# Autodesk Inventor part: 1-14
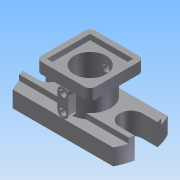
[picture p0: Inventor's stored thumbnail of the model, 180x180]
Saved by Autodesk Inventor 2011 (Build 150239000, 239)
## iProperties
Created: 2014-02
Part Number: 1-14
Document SubType Name: Modeling
Designer: Administrator
Density: 1 g/cm^3
Author: Administrator
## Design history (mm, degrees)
sketch "草图1"
  geometry: L1 (-18.455, 10.02)-(18.455, 10.02); L2 (-18.458, -10.014)-(18.458, -10.014); L3 (-15, -4.223)-(-20.571, -4.223); L4 (0, 0)-(0, 18.978); L5 (0.467, 0.003)-(27.339, 0.003); L6 (-15, 4.229)-(-20.571, 4.229); L7 (15, 4.229)-(20.571, 4.229); L8 (15, -4.223)-(20.571, -4.223); A1 r 4.226 centre (-15, 0.003) between (-15, -4.223) and (-15, 4.229); A2 r 4.226 centre (15, 0.003) between (15, 4.229) and (15, -4.223); A3 r 21 centre (0, 0) between (-18.455, 10.02) and (-20.57, 4.229); A4 r 21 centre (0, 0) between (-20.571, -4.223) and (-18.458, -10.014); A5 r 21 centre (0, 0) between (18.458, -10.014) and (20.571, -4.223); A6 r 21 centre (0, 0) between (20.57, 4.229) and (18.455, 10.02); 4 further points
  constraints: 16 end point, 13 point on circle, 7 symmetric about line, 6 centre point, 3 point on line, 1 coincident, 1 horizontal, 1 parallel, 1 perpendicular, 1 tangent, 1 other
  dimensions: "d27" = 20.03478 distance between parallel lines of L1 L2; "d29" = 30 diameter of A1.centre L4
extrude "拉伸1" new body sketch "草图1" distance "d0" = 6; taper "d1" = 0 deg
sketch "草图2"
  geometry: C1 r 7.5 at (0, 0); 1 further point
  constraints: 1 centre point, 1 coincident
  dimensions: "d2" = 15 diameter of C1
extrude "拉伸2" join sketch "草图2" distance "d3" = 10; taper "d4" = 0 deg
sketch "草图3"
  geometry: L1 (-9.935, -9.95)-(9.935, -9.95); L2 (9.935, -9.95)-(9.935, 9.921); L3 (9.935, 9.921)-(-9.935, 9.921); L4 (-9.935, 9.921)-(-9.935, -9.95); C1 r 7.5 at (0, 0) reference; 1 further point
  constraints: 8 end point, 2 parallel, 1 horizontal, 1 midpoint, 1 perpendicular, 1 vertical alignment
  dimensions: "d5" = 19.87123 distance of L1.end L2.end; "d6" = 19.871 distance of L2.end L3.end
extrude "拉伸3" join sketch "草图3" distance "d7" = 4; taper "d8" = 0 deg
fillet "圆角1" dims "d9" = 2
fillet "圆角2" dims "d10" = 2
sketch "草图4"
  geometry: L1 (-7.935, -7.95)-(7.935, -7.95); L2 (7.935, -7.95)-(7.935, 7.921); L3 (7.935, 7.921)-(-7.935, 7.921); L4 (-7.935, 7.921)-(-7.935, -7.95); A1 r 2 centre (-7.935, -7.95) between (-9.935, -7.95) and (-7.935, -9.95) reference; A2 r 2 centre (7.935, 7.921) between (9.935, 7.921) and (7.935, 9.921) reference; 1 further point
  constraints: 8 end point, 2 parallel, 1 horizontal, 1 perpendicular
extrude "拉伸4" cut sketch "草图4" distance "d11" = 2; taper "d12" = 0 deg
sketch "草图5"
  geometry: C1 r 5.899 at (0, 0); 1 further point
  constraints: 1 centre point, 1 coincident
extrude "拉伸5" cut sketch "草图5" stored distance "d13" = 2; taper "d14" = 0 deg
sketch "草图7"
  geometry: L1 (10.523, 16)-(26.394, 16) reference; L2 (10.958, 6)-(10.958, 16) reference; L3 (25.958, 6)-(25.958, 16) reference; L4 (20.458, 7.999)-(20.458, 13.997); L5 (16.458, 13.997)-(16.458, 8.001); A1 r 2 centre (18.458, 8.001) between (16.458, 8.001) and (20.458, 8.004); A2 r 2 centre (18.458, 13.997) between (20.458, 13.997) and (16.458, 13.997); 2 further points
  constraints: 5 point on circle, 4 end point, 3 tangent, 2 centre point, 2 vertical alignment, 1 midpoint, 1 point on line
extrude "拉伸7" join sketch "草图7" stored distance "d19" = 2; taper "d20" = 0 deg
sketch "草图8"
  geometry: C1 r 1.25 at (18.458, 13.997); C2 r 1.25 at (18.458, 8.001); A1 r 2 centre (18.458, 13.997) between (20.458, 13.997) and (16.458, 13.997) reference; A2 r 2 centre (18.458, 8.001) between (16.458, 8.001) and (20.458, 7.999) reference; 1 further point
  constraints: 2 centre point, 2 coincident
  dimensions: "d21" = 2.5 diameter of C1; "d22" = 2.5 diameter of C2
extrude "拉伸8" cut sketch "草图8" stored distance "d23" = 2; taper "d24" = 0 deg
sketch "草图9"
  geometry: L1 (20.121, -6.011)-(4.486, -6.011); L2 (20.12, 6.017)-(4.478, 6.017); L3 (-20.121, -6.011)-(-4.486, -6.011); L4 (-20.12, 6.017)-(-4.478, 6.017); L5 (-15, 4.229)-(-20.57, 4.229) reference; L6 (-9.935, -7.95)-(-9.935, 7.921) reference; L7 (20.57, 4.229)-(15, 4.229) reference; L8 (15, -4.223)-(20.571, -4.223) reference; L9 (-20.571, -4.223)-(-15, -4.223) reference; A1 r 7.5 centre (0, 0) between (4.486, -6.011) and (4.478, 6.017) reference; A2 r 21 centre (0, 0) between (20.57, 4.229) and (18.455, 10.02) reference; A3 r 21 centre (0, 0) between (-18.455, 10.02) and (-20.57, 4.229) reference; A4 r 21 centre (0, 0) between (-20.571, -4.223) and (-18.458, -10.014) reference; A5 r 21 centre (0, 0) between (18.458, -10.014) and (20.571, -4.223) reference; A6 r 4.226 centre (-15, 0.003) between (-15, -4.223) and (-15, 4.229) reference; A7 r 4.226 centre (15, 0.003) between (15, 4.229) and (15, -4.223) reference
  constraints: 8 end point, 8 point on circle, 3 parallel
extrude "拉伸10" join sketch "草图9" distance "d31" = 2; taper "d32" = 0 deg
node "实体1"
other parameters: "d30" = 21
